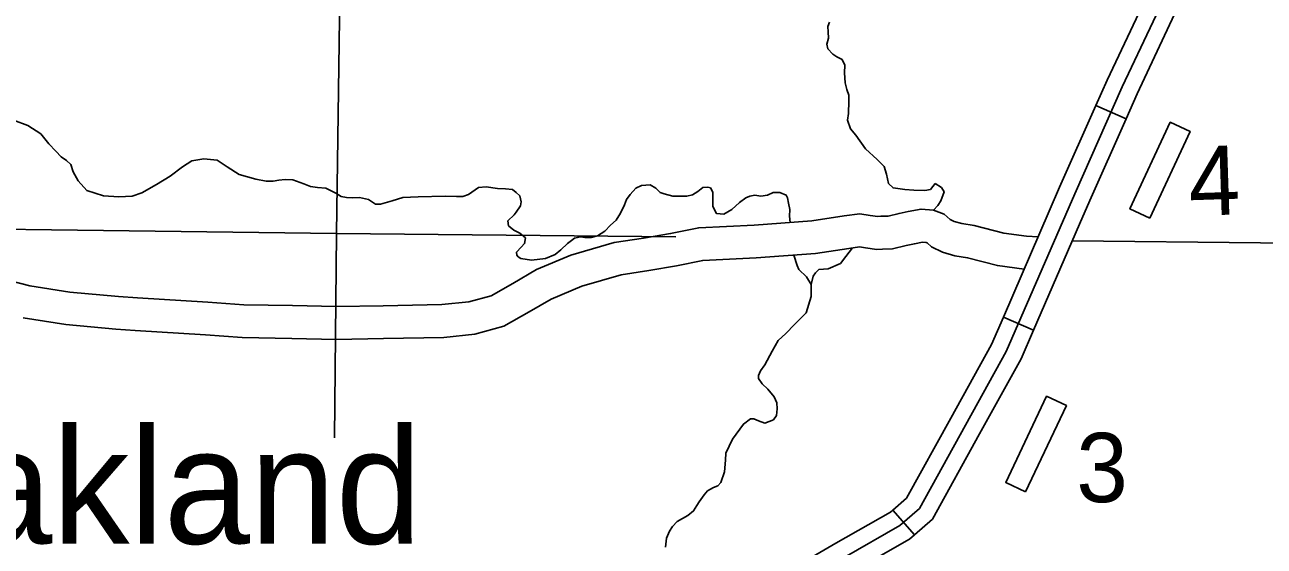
# Model space of a CAD drawing. Extents: x 1369979 to 1371646, y 379997 to 381064.
# Drawn here: x 1371021.7 to 1371088, y 380461.7 to 380489.6 of the extents above; entities that cross this region are included whole.
import ezdxf

# ---------------------------------------------------------------- set-up
doc = ezdxf.new("R2010")
doc.units = 0
doc.layers.add('R_Border Notes', color=7, linetype='Continuous')

msp = doc.modelspace()

# ---------------------------------------------------------------- linework, layer by layer
at = {"layer": 'R_Border Notes'}
for p, q in [((1371080.628, 380484.582), (1371079.021, 380485.295)), ((1371074.063, 380473.948), (1371075.677, 380473.25)), ((1371069.3, 380462.281), (1371068.145, 380463.606)), ((1371068.145, 380463.606), (1371068.145, 380463.606))]:
    msp.add_line(p, q, dxfattribs=at)
for points in [[(1371039.069, 380539.9), (1371038.802, 380509.143), (1371038.361, 380478.435)], [(1371037.435, 380412.892), (1371037.435, 380418.777), (1371037.542, 380426.57), (1371037.595, 380431.198), (1371037.542, 380435.451), (1371037.702, 380438.661), (1371037.809, 380440.408), (1371038.29, 380442.173), (1371038.798, 380443.591), (1371039.733, 380445.169), (1371041.39, 380446.614), (1371043.1, 380447.764), (1371045.212, 380448.727), (1371046.86, 380449.763), (1371051.083, 380452.277), (1371059.603, 380457.611), (1371065.535, 380461.062), (1371068.528, 380462.774), (1371069.571, 380463.684), (1371074.221, 380472.099), (1371077.882, 380480.558), (1371080.421, 380486.283), (1371083.735, 380493.318), (1371084.954, 380496.125)], [(1371079.021, 380485.295), (1371079.621, 380486.648), (1371081.636, 380490.925)], [(1371065.583, 380487.455), (1371065.432, 380487.746), (1371065.144, 380487.898), (1371064.932, 380488.034), (1371064.674, 380488.322), (1371064.613, 380488.58), (1371064.704, 380488.899), (1371064.689, 380489.233), (1371064.674, 380489.521), (1371064.75, 380489.764)], [(1371080.628, 380484.582), (1371081.22, 380485.917), (1371083.226, 380490.176)], [(1371022.537, 380483.774), (1371021.843, 380484.222), (1371021.085, 380484.495), (1371020.403, 380484.783), (1371019.964, 380485.086), (1371019.585, 380485.466), (1371019.282, 380485.814), (1371019.191, 380486.209), (1371019.055, 380487.483), (1371018.782, 380488.333), (1371018.539, 380488.97), (1371018.494, 380489.182)], [(1371070.418, 380481.113), (1371070.16, 380480.795), (1371069.857, 380480.734), (1371069.266, 380480.749), (1371068.796, 380480.795), (1371068.16, 380480.871), (1371067.917, 380481.113), (1371067.811, 380481.614), (1371067.69, 380482.024), (1371067.311, 380482.388), (1371066.69, 380482.964), (1371066.175, 380483.708), (1371065.887, 380484.041), (1371065.72, 380484.512), (1371065.78, 380484.86), (1371065.796, 380485.528), (1371065.796, 380485.847), (1371065.69, 380486.15), (1371065.599, 380486.499), (1371065.553, 380487.045), (1371065.583, 380487.455)], [(1371079.021, 380485.295), (1371077.077, 380480.911), (1371076.521, 380479.627)], [(1371078.134, 380478.928), (1371078.687, 380480.205), (1371080.628, 380484.582)], [(1371027.948, 380480.603), (1371027.433, 380480.421), (1371026.72, 380480.391), (1371025.887, 380480.452), (1371025.008, 380480.725), (1371024.538, 380481.256), (1371024.28, 380481.726), (1371024.144, 380482.136), (1371023.916, 380482.348), (1371023.628, 380482.53), (1371023.341, 380482.849), (1371022.962, 380483.243), (1371022.537, 380483.774)], [(1371034.049, 380481.347), (1371033.161, 380481.59), (1371032.51, 380481.999), (1371031.979, 380482.363), (1371031.267, 380482.424), (1371030.63, 380482.318), (1371030.13, 380481.999), (1371029.463, 380481.498), (1371028.736, 380481.059), (1371027.948, 380480.603)], [(1371038.323, 380480.588), (1371037.793, 380480.861), (1371037.353, 380480.892), (1371036.974, 380480.952), (1371036.611, 380481.089), (1371036.035, 380481.301), (1371035.626, 380481.316), (1371035.277, 380481.286), (1371034.974, 380481.225), (1371034.61, 380481.225), (1371034.049, 380481.347)], [(1371070.709, 380480.182), (1371070.888, 380480.658), (1371070.751, 380480.886), (1371070.418, 380481.113)], [(1371048.805, 380477.008), (1371048.235, 380477.084), (1371048.099, 380477.175), (1371048.023, 380477.266), (1371048.008, 380477.433), (1371048.25, 380477.691), (1371048.432, 380477.888), (1371048.477, 380478.191), (1371048.174, 380478.449), (1371047.856, 380478.616), (1371047.583, 380478.844), (1371047.538, 380479.102), (1371047.886, 380479.435), (1371047.992, 380479.572), (1371048.22, 380479.906), (1371048.25, 380480.133), (1371048.174, 380480.452), (1371047.977, 380480.619), (1371047.795, 380480.785), (1371047.417, 380480.831), (1371046.977, 380480.846), (1371046.371, 380480.937), (1371045.962, 380480.892), (1371045.431, 380480.512), (1371045.128, 380480.406), (1371044.795, 380480.406), (1371044.188, 380480.437), (1371042.734, 380480.391), (1371041.915, 380480.361), (1371041.339, 380480.179), (1371040.718, 380479.997), (1371040.46, 380479.997), (1371040.081, 380480.255), (1371039.596, 380480.361), (1371039.233, 380480.346), (1371038.899, 380480.361), (1371038.626, 380480.406), (1371038.323, 380480.588)], [(1371048.805, 380477.008), (1371049.563, 380477.084), (1371050.078, 380477.311), (1371050.381, 380477.554), (1371050.73, 380477.888), (1371050.942, 380478.055), (1371051.108, 380478.176), (1371051.427, 380478.252), (1371051.654, 380478.222), (1371052.003, 380478.222), (1371052.336, 380478.298), (1371052.73, 380478.555), (1371053.033, 380478.874), (1371053.336, 380479.147), (1371053.564, 380479.511), (1371053.776, 380479.966), (1371053.882, 380480.255), (1371054.094, 380480.528), (1371054.382, 380480.861), (1371054.7, 380480.998), (1371055.155, 380481.043), (1371055.458, 380480.861), (1371055.685, 380480.634), (1371055.913, 380480.558), (1371056.367, 380480.421), (1371056.777, 380480.421), (1371057.125, 380480.437), (1371057.428, 380480.497), (1371057.701, 380480.679), (1371057.974, 380480.892), (1371058.247, 380480.907), (1371058.383, 380480.877), (1371058.519, 380480.649), (1371058.519, 380480.103), (1371058.519, 380479.875), (1371058.716, 380479.496), (1371059.095, 380479.466), (1371059.52, 380479.724), (1371059.944, 380480.088), (1371060.278, 380480.346), (1371060.49, 380480.421), (1371060.762, 380480.482), (1371061.081, 380480.437), (1371061.444, 380480.482), (1371061.748, 380480.619), (1371062.096, 380480.634), (1371062.445, 380480.482), (1371062.505, 380480.346), (1371062.566, 380480.057), (1371062.642, 380479.724)], [(1371019.858, 380476.151), (1371021.95, 380475.631), (1371024.089, 380475.293), (1371026.7, 380475.056), (1371027.716, 380474.977), (1371031.475, 380474.749), (1371033.406, 380474.604), (1371036.015, 380474.564), (1371038.353, 380474.511), (1371040.859, 380474.55), (1371044.008, 380474.617), (1371045.451, 380474.766), (1371046.649, 380475.092), (1371047.804, 380475.756), (1371049.067, 380476.493), (1371050.917, 380477.27), (1371053.227, 380477.943), (1371054.799, 380478.178), (1371056.247, 380478.428), (1371057.756, 380478.733), (1371060.733, 380478.883), (1371063.815, 380479.107), (1371065.54, 380479.37), (1371066.38, 380479.481), (1371066.936, 380479.397), (1371067.352, 380479.342), (1371067.509, 380479.352), (1371067.897, 380479.363), (1371068.479, 380479.505), (1371068.969, 380479.604), (1371069.657, 380479.735), (1371070.315, 380479.673), (1371070.892, 380479.472), (1371071.215, 380479.179), (1371071.432, 380479.071), (1371071.836, 380478.959), (1371072.507, 380478.853), (1371074.087, 380478.441), (1371075.308, 380478.279), (1371075.924, 380478.246)], [(1371070.321, 380479.671), (1371070.557, 380479.924), (1371070.709, 380480.182)], [(1371062.642, 380479.724), (1371062.608, 380479.359), (1371062.651, 380479.022)], [(1371076.521, 380479.627), (1371074.063, 380473.948)], [(1371005.072, 380478.851), (1371038.361, 380478.435)], [(1371038.361, 380478.435), (1371038.264, 380467.478)], [(1371038.361, 380478.435), (1371056.532, 380478.25)], [(1371075.677, 380473.25), (1371078.134, 380478.928)], [(1371021.601, 380473.906), (1371023.872, 380473.548), (1371026.552, 380473.304), (1371027.594, 380473.223), (1371031.355, 380472.995), (1371033.326, 380472.847), (1371035.982, 380472.806), (1371038.347, 380472.753), (1371040.892, 380472.793), (1371044.117, 380472.861), (1371045.774, 380473.032), (1371047.329, 380473.455), (1371048.685, 380474.235), (1371049.854, 380474.917), (1371051.505, 380475.611), (1371053.604, 380476.222), (1371055.079, 380476.442), (1371056.571, 380476.7), (1371057.975, 380476.984), (1371060.84, 380477.128), (1371064.012, 380477.359), (1371065.788, 380477.63), (1371066.363, 380477.706), (1371066.69, 380477.657), (1371067.289, 380477.578), (1371067.586, 380477.595), (1371068.134, 380477.611), (1371068.861, 380477.789), (1371069.306, 380477.878), (1371069.741, 380477.961), (1371069.938, 380477.943), (1371069.976, 380477.929), (1371070.214, 380477.715), (1371070.799, 380477.422), (1371071.464, 380477.238), (1371072.148, 380477.131), (1371073.748, 380476.713), (1371075.178, 380476.523)], [(1371077.748, 380478.035), (1371097.913, 380477.83)], [(1371061.297, 380471.397), (1371061.692, 380472.116), (1371062.01, 380472.692), (1371062.419, 380473.072), (1371062.889, 380473.557), (1371063.51, 380474.179), (1371063.783, 380475.059), (1371063.783, 380475.696), (1371063.874, 380476.136), (1371064.01, 380476.318), (1371064.192, 380476.5), (1371064.677, 380476.53), (1371065.344, 380476.819), (1371065.632, 380477.198), (1371065.985, 380477.66)], [(1371062.843, 380477.274), (1371063.018, 380476.705), (1371063.109, 380476.492), (1371063.533, 380476.098), (1371063.783, 380475.696)], [(1371071.249, 380468.539), (1371073.431, 380472.487), (1371074.063, 380473.948)], [(1371072.788, 380467.689), (1371075.011, 380471.711), (1371075.677, 380473.25)], [(1371058.945, 380465.075), (1371059.145, 380465.662), (1371059.191, 380466.284), (1371059.206, 380466.664), (1371059.57, 380467.407), (1371060.146, 380468.211), (1371060.525, 380468.499), (1371060.706, 380468.499), (1371060.964, 380468.393), (1371061.297, 380468.272), (1371061.752, 380468.439), (1371061.919, 380468.681), (1371061.964, 380469.03), (1371061.934, 380469.349), (1371061.798, 380469.683), (1371061.449, 380470.092), (1371061.161, 380470.38), (1371060.949, 380470.653), (1371060.949, 380470.82), (1371061.07, 380471.063), (1371061.297, 380471.397)], [(1371068.145, 380463.606), (1371068.876, 380464.244), (1371071.249, 380468.539)], [(1371069.301, 380462.281), (1371070.265, 380463.123), (1371072.788, 380467.689)], [(1371055.975, 380461.62), (1371056.036, 380462.094), (1371056.195, 380462.474), (1371056.346, 380462.732), (1371056.611, 380462.997), (1371057.172, 380463.316), (1371057.483, 380463.558), (1371057.65, 380463.847), (1371057.778, 380464.051), (1371058.044, 380464.415), (1371058.233, 380464.628), (1371058.544, 380464.817), (1371058.779, 380464.908), (1371058.945, 380465.075)], [(1371068.145, 380463.606), (1371068.016, 380463.494), (1371065.096, 380461.823), (1371062.948, 380460.574)], [(1371063.832, 380459.055), (1371065.974, 380460.301), (1371069.041, 380462.054), (1371069.3, 380462.281)]]:
    msp.add_lwpolyline(points, dxfattribs=at)
for points in [[(1371081.902, 380479.251), (1371080.838, 380479.744), (1371082.994, 380484.395), (1371084.058, 380483.903)], [(1371075.246, 380464.574), (1371074.187, 380465.076), (1371076.38, 380469.71), (1371077.439, 380469.209)]]:
    msp.add_lwpolyline(points, close=True, dxfattribs=at)

# ---------------------------------------------------------------- texts
msp.add_text('4', height=3.712, rotation=1.84934, dxfattribs=at).set_placement((1371084.026, 380479.368))
for s, height, p in [('Oakland', 6.1875, (1371012.114, 380461.801)), ('3', 3.712, (1371077.966, 380464.031))]:
    msp.add_text(s, height=height, dxfattribs=at).set_placement(p)

doc.saveas('drawing.dxf')
